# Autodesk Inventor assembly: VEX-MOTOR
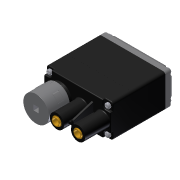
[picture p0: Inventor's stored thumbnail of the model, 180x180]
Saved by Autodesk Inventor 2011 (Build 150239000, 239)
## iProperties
Created: 2007-08
Part Number: VEX-MOTOR
Document SubType Name: Assembly
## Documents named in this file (9)
- C:\Data Folder\VEX 2011\Inventor Datasets\Unit 15\Components\VEX_Motor_Animate.iam
- C:\Data Folder\VEX 2011\Inventor Datasets\Unit 15\Components\Insert-Nut-632-Simple.ipt
- C:\Data Folder\VEX 2011\Inventor Datasets\Unit 15\Components\Vex-Motor-Top-Housing.ipt
- C:\Data Folder\VEX 2011\Inventor Datasets\Unit 15\Components\Vex-Motor-Output-Gear.ipt
- C:\Data Folder\VEX 2011\Inventor Datasets\Unit 15\Components\Vex-Motor-Bottom-Plate.ipt
- C:\Data Folder\VEX 2011\Inventor Datasets\Unit 15\Components\Vex-Motor-Bottom-Housing.ipt
- C:\Data Folder\VEX 2011\Inventor Datasets\Unit 15\Components\Vex-Wire-Support.ipt
- C:\Data Folder\VEX 2011\Inventor Datasets\Unit 15\Components\CLUTCH.iam
- C:\Data Folder\VEX 2011\Inventor Datasets\Unit 15\Components\Machine Screws.iam
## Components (9 placed, 8 different names)
1. Vex-Motor-Top-Housing — Insert:2, Mate:3, Mate:4, Mate:5, Mate:15, Mate:16, Insert:3
2. Vex-Motor-Bottom-Housing — Mate:3, Mate:4, Mate:5, Mate:6, Mate:7, Mate:8
3. Vex-Motor-Bottom-Plate — Mate:6, Mate:7, Mate:8, Mate:9, Mate:10, Mate:11
4. Insert-Nut-632-Simple — Mate:15
5. Insert-Nut-632-Simple — Mate:16
6. Vex-Motor-Output-Gear — Insert:1, Insert:2, Angle:1
7. Vex-Wire-Support — Mate:9, Mate:10, Mate:11
8. CLUTCH:1 [sub-assembly] — Insert:1, Angle:1
9. Machine Screws:1 [sub-assembly] — Insert:3
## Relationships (15: Mate 11, Insert 3, Angle 1)
- Insert:1: Vex-Motor-Output-Gear ↔ CLUTCH:1
- Insert:2: Vex-Motor-Top-Housing ↔ Vex-Motor-Output-Gear
- Mate:3: Vex-Motor-Top-Housing ↔ Vex-Motor-Bottom-Housing
- Mate:4: Vex-Motor-Top-Housing ↔ Vex-Motor-Bottom-Housing
- Mate:5: Vex-Motor-Top-Housing ↔ Vex-Motor-Bottom-Housing
- Mate:6: Vex-Motor-Bottom-Housing ↔ Vex-Motor-Bottom-Plate
- Mate:7: Vex-Motor-Bottom-Housing ↔ Vex-Motor-Bottom-Plate
- Mate:8: Vex-Motor-Bottom-Housing ↔ Vex-Motor-Bottom-Plate
- Mate:9: Vex-Motor-Bottom-Plate ↔ Vex-Wire-Support
- Mate:10: Vex-Motor-Bottom-Plate ↔ Vex-Wire-Support
- Mate:11: Vex-Motor-Bottom-Plate ↔ Vex-Wire-Support
- Angle:1: Vex-Motor-Output-Gear ↔ CLUTCH:1
- Mate:15: Vex-Motor-Top-Housing ↔ Insert-Nut-632-Simple
- Mate:16: Vex-Motor-Top-Housing ↔ Insert-Nut-632-Simple
- Insert:3: Vex-Motor-Top-Housing ↔ Machine Screws:1
